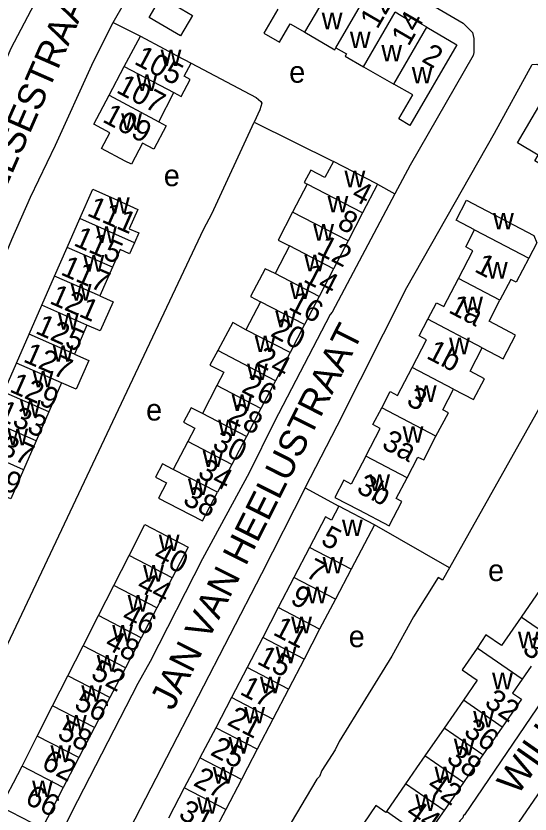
# Model space of a CAD drawing. Extents: x 159700 to 161346, y 381730 to 382922.
# Drawn here: x 160744.8 to 160840.3, y 381991.4 to 382139.7 of the extents above; entities that cross this region are included whole.
import ezdxf

# ---------------------------------------------------------------- set-up
doc = ezdxf.new("R2010")
doc.units = 0
for name, color, linetype in [('BLT_Basislijn', 7, 'Continuous'), ('BLT_Bebouwing', 7, 'Continuous'), ('BLT_Centroide', 7, 'Continuous'), ('BLT_Huisnummer', 7, 'Continuous'), ('BLT_Huisnummer_ tussenligend', 7, 'Continuous'), ('BLT_Onderverdeling_panden', 7, 'Continuous'), ('BLT_Straatnaam', 7, 'Continuous')]:
    doc.layers.add(name, color=color, linetype=linetype)

msp = doc.modelspace()

# ---------------------------------------------------------------- linework, layer by layer
at = {"layer": 'BLT_Basislijn'}
for p, q in [((160762.83, 382138.43), (160767.88, 382135.88)), ((160789.01, 382119.93), (160803.75, 382112.64)), ((160811.93, 382108.39), (160815.18, 382106.64)), ((160798.48, 382052.02), (160804.76, 382048.6)), ((160825.28, 382037.17), (160811.35, 382045.16))]:
    msp.add_line(p, q, dxfattribs=at)
for points in [[(160762.83, 382138.43), (160777.07, 382163.35), (160777.98, 382164.11), (160779.97, 382165.1)], [(160779.97, 382165.1), (160782.68, 382164.9), (160783.96, 382164.37), (160786.64, 382162.49), (160793.84, 382158.54), (160804.07, 382152.25), (160827.87, 382138.34), (160829.56, 382136.57), (160829.84, 382135.46), (160829.82, 382132.85), (160829.69, 382132.32), (160817.98, 382111.93), (160815.18, 382106.64)], [(160736.77, 382117.18), (160743.9, 382133.7), (160755.59, 382155.95), (160755.73, 382156.22)], [(160715.43, 382001.34), (160706.86, 382005.62), (160706.44, 382006.13), (160706.37, 382006.99), (160712.72, 382022.39), (160715.55, 382029.86), (160718.04, 382035.66), (160727.65, 382059.9), (160733.57, 382072.85), (160744.01, 382098.14), (160747.46, 382106.03), (160752.09, 382115.65), (160758.89, 382130.51), (160762.59, 382138.01), (160762.83, 382138.43)], [(160777.33, 382130.86), (160789.38, 382124.51), (160790.24, 382123.78), (160790.46, 382123.46), (160790.08, 382122.22), (160789.01, 382119.93)], [(160798.48, 382052.02), (160804.47, 382063.53), (160817.41, 382089.21), (160833.68, 382117.89), (160840.69, 382130.67), (160841.52, 382130.73), (160858.53, 382121.03), (160862.21, 382118.57), (160868.46, 382114.9), (160869.55, 382114.27)], [(160729.44, 381993.93), (160779.67, 382100.1), (160781.16, 382102.9), (160789.01, 382119.93)], [(160815.18, 382106.64), (160803.51, 382084.65), (160803.12, 382084.2), (160792.72, 382064.24), (160788.1, 382054.81), (160779.42, 382038.85), (160769.7, 382019.74), (160767.41, 382015.7), (160755.12, 381991.74), (160751.34, 381984.02), (160750.55, 381983.57), (160749.53, 381983.44), (160729.44, 381993.93)], [(160855.2, 382089.81), (160851, 382082.65), (160843.02, 382068.68), (160825.28, 382037.17)], [(160883.99, 382072.81), (160870.54, 382052.66), (160865.04, 382045.05), (160858.65, 382035.7), (160858.47, 382035.66), (160858.03, 382034.8), (160853.13, 382028.14), (160852.91, 382027.61), (160852.73, 382027.57), (160828.11, 381991.25), (160827.9, 381991.18), (160827.79, 381990.75), (160827.27, 381990.23), (160823.65, 381984.68), (160823.44, 381984.61), (160821.73, 381981.82), (160817.59, 381976.14), (160816.77, 381975.28), (160804.69, 381957.09), (160803.57, 381956.03), (160800.6, 381955.73), (160797.89, 381956.96), (160781.74, 381965.52)], [(160798.48, 382052.02), (160790.41, 382036.07), (160760.95, 381979.11), (160761.51, 381976.41), (160762.27, 381975.47), (160781.74, 381965.52)], [(160825.28, 382037.17), (160824.03, 382034.87), (160823.19, 382035.33), (160818.63, 382028.05), (160814.57, 382020.77), (160804.81, 382004.89), (160804.06, 382003.36), (160801.59, 381999.49), (160801.14, 381998.42), (160800.64, 381997.89), (160789.12, 381978.49), (160785.84, 381973.29), (160781.74, 381965.52)], [(160855.12, 382014.54), (160854.65, 382013.88), (160825.11, 381970.95)]]:
    msp.add_lwpolyline(points, dxfattribs=at)
at = {"layer": 'BLT_Bebouwing'}
for p, q in [((160764.9, 382130.27), (160767.88, 382135.88)), ((160762.06, 382124.92), (160764.9, 382130.27)), ((160809.33, 382130.23), (160814.97, 382127)), ((160771.31, 382120.01), (160774.1, 382125.44)), ((160811.93, 382108.39), (160809.17, 382103.07)), ((160809.17, 382103.07), (160806.47, 382097.88)), ((160754.29, 382096.67), (160756.65, 382102.04)), ((160806.47, 382097.88), (160803.77, 382092.69)), ((160751.93, 382091.3), (160754.29, 382096.67)), ((160762.69, 382092.99), (160760.34, 382087.65)), ((160803.77, 382092.69), (160801.1, 382087.55)), ((160749.58, 382085.92), (160751.93, 382091.3)), ((160801.1, 382087.55), (160798.39, 382082.34)), ((160790.2, 382086.59), (160787.49, 382081.38)), ((160747.22, 382080.55), (160749.58, 382085.92)), ((160757.97, 382082.24), (160755.62, 382076.86)), ((160798.39, 382082.34), (160795.68, 382077.12)), ((160744.86, 382075.17), (160747.22, 382080.55)), ((160795.68, 382077.12), (160792.97, 382071.91)), ((160742.51, 382069.8), (160744.86, 382075.17)), ((160753.26, 382071.49), (160750.9, 382066.12)), ((160792.97, 382071.91), (160790.28, 382066.75)), ((160782.09, 382071), (160779.4, 382065.82)), ((160790.28, 382066.75), (160787.58, 382061.56)), ((160750.9, 382066.12), (160748.55, 382060.74)), ((160748.55, 382060.74), (160746.19, 382055.37)), ((160787.58, 382061.56), (160784.88, 382056.37)), ((160776.7, 382060.63), (160774, 382055.44)), ((160784.88, 382056.37), (160782.19, 382051.18)), ((160802.28, 382046.61), (160799.31, 382040.91)), ((160811.35, 382045.16), (160807.02, 382036.88)), ((160799.31, 382040.91), (160796.4, 382035.34)), ((160762.97, 382033.87), (160765.81, 382039.46)), ((160807.02, 382036.88), (160804.12, 382031.32)), ((160773.82, 382035.3), (160770.93, 382029.74)), ((160796.4, 382035.34), (160793.5, 382029.76)), ((160760.12, 382028.28), (160762.97, 382033.87)), ((160842.13, 382033.13), (160838.59, 382028.01)), ((160804.12, 382031.32), (160801.17, 382025.77)), ((160770.93, 382029.74), (160768.03, 382024.17)), ((160793.5, 382029.76), (160790.62, 382024.24)), ((160757.28, 382022.69), (160760.12, 382028.28)), ((160801.17, 382025.77), (160798.32, 382020.22)), ((160768.03, 382024.17), (160765.14, 382018.6)), ((160790.62, 382024.24), (160787.71, 382018.65)), ((160754.43, 382017.1), (160757.28, 382022.69)), ((160798.32, 382020.22), (160795.4, 382014.63)), ((160765.14, 382018.6), (160762.24, 382013.04)), ((160787.71, 382018.65), (160784.79, 382013.06)), ((160840.49, 382018.92), (160838.8, 382016.48)), ((160751.59, 382011.5), (160754.43, 382017.1)), ((160838.8, 382016.48), (160837.02, 382013.89)), ((160795.4, 382014.63), (160792.49, 382009.04)), ((160762.24, 382013.04), (160759.35, 382007.47)), ((160784.79, 382013.06), (160781.88, 382007.46)), ((160827.9, 382012.57), (160824.32, 382007.4)), ((160748.74, 382005.91), (160751.59, 382011.5)), ((160792.49, 382009.04), (160789.57, 382003.45)), ((160759.35, 382007.47), (160756.45, 382001.9)), ((160781.88, 382007.46), (160778.96, 382001.87)), ((160824.32, 382007.4), (160820.74, 382002.23)), ((160835.08, 382007.59), (160831.47, 382002.44)), ((160786.65, 381997.86), (160783.73, 381992.27)), ((160817.16, 381997.06), (160813.58, 381991.9)), ((160827.88, 381997.28), (160824.3, 381992.11)), ((160776.05, 381996.28), (160773.13, 381990.68)), ((160783.73, 381992.27), (160780.81, 381986.67)), ((160824.3, 381992.11), (160820.73, 381986.94))]:
    msp.add_line(p, q, dxfattribs=at)
for points in [[(160781.42, 382146.23), (160778.2, 382148.11), (160774.4, 382141.59), (160777.55, 382139.75), (160775.34, 382135.97), (160773.84, 382136.84), (160769.52, 382139.36), (160781.77, 382160.35), (160787.63, 382156.93), (160787.38, 382156.48)], [(160793.41, 382140.93), (160790.82, 382136.49), (160793.74, 382134.79), (160795.74, 382138.21), (160798.45, 382136.63)], [(160821.09, 382137.55), (160818.05, 382139.32), (160817.77, 382138.84), (160815.2, 382140.34)], [(160798.45, 382136.63), (160804.02, 382133.38)], [(160821.09, 382137.55), (160826.69, 382134.27), (160817.97, 382119.33), (160815.9, 382120.54), (160818.49, 382124.99), (160814.97, 382127)], [(160767.88, 382135.88), (160772.29, 382133.53), (160774.61, 382132.3), (160777.33, 382130.86)], [(160804.02, 382133.38), (160804.22, 382133.73)], [(160804.22, 382133.73), (160806.15, 382132.6), (160805.91, 382132.19), (160809.33, 382130.23)], [(160774.1, 382125.44), (160775.45, 382124.72), (160777.14, 382127.88), (160776.03, 382128.47), (160777.33, 382130.86)], [(160771.31, 382120.01), (160772.69, 382119.27), (160770.38, 382114.92), (160768.31, 382116.02), (160766.23, 382112.11), (160765.09, 382112.71), (160760.67, 382115.05), (160762.23, 382117.97), (160759.22, 382119.57), (160762.06, 382124.92)], [(160845.48, 382110.24), (160841.18, 382112.78), (160841.78, 382113.81), (160837.92, 382116.09), (160842.33, 382123.57), (160847.52, 382120.51), (160848.28, 382121.81), (160851.26, 382120.05)], [(160803.75, 382112.64), (160802.18, 382109.63), (160799.52, 382111.01), (160798.32, 382108.71), (160798.88, 382108.41)], [(160811.93, 382108.39), (160807.5, 382110.69), (160803.75, 382112.64)], [(160798.88, 382108.41), (160796.17, 382103.2)], [(160756.65, 382102.04), (160759.03, 382107.48), (160763.61, 382105.47), (160767.4, 382103.73), (160765.83, 382100.15), (160767.59, 382099.37), (160766.77, 382097.52)], [(160829.98, 382099.92), (160826.52, 382101.73), (160828.47, 382105.45), (160840.98, 382098.91), (160841.55, 382097.53), (160840.05, 382094.65)], [(160796.17, 382103.2), (160793.49, 382098.04), (160795.59, 382096.95)], [(160826.96, 382090.89), (160829.67, 382096.05), (160828.33, 382096.75), (160829.98, 382099.92)], [(160766.77, 382097.52), (160765.88, 382095.49), (160764.12, 382096.26), (160762.69, 382092.99)], [(160795.59, 382096.95), (160792.91, 382091.8)], [(160840.05, 382094.65), (160837.71, 382090.19), (160836.69, 382090.72), (160834.67, 382086.86)], [(160792.91, 382091.8), (160791.05, 382092.72), (160788.35, 382087.53), (160790.2, 382086.59)], [(160821.31, 382083.32), (160822.92, 382086.38), (160824.24, 382085.69), (160826.96, 382090.89)], [(160760.34, 382087.65), (160762.82, 382086.56), (160760.44, 382081.15), (160757.97, 382082.24)], [(160831.4, 382078.01), (160835.26, 382075.98), (160837.59, 382080.4), (160833.72, 382082.44), (160832.65, 382083), (160834.67, 382086.86)], [(160818.37, 382074.39), (160821.06, 382079.52), (160819.7, 382080.23), (160821.31, 382083.32)], [(160787.49, 382081.38), (160785.06, 382082.7), (160782.27, 382077.51)], [(160782.27, 382077.51), (160780.81, 382074.8), (160783.38, 382073.47), (160782.09, 382071)], [(160826.07, 382070.36), (160829.77, 382068.42), (160831.79, 382072.27), (160829.13, 382073.67), (160831.4, 382078.01)], [(160755.62, 382076.86), (160758.3, 382075.68), (160755.95, 382070.32), (160753.26, 382071.49)], [(160812.71, 382066.86), (160814.29, 382069.88), (160815.65, 382069.18), (160818.37, 382074.39)], [(160822.8, 382061.58), (160825.1, 382065.96), (160824.05, 382066.51), (160826.07, 382070.36)], [(160779.4, 382065.82), (160777.31, 382066.9), (160775.9, 382064.19), (160777.99, 382063.11), (160776.7, 382060.63)], [(160809.74, 382057.91), (160812.43, 382063.05), (160811.08, 382063.75), (160812.71, 382066.86)], [(160817.44, 382053.89), (160819.45, 382057.74), (160820.51, 382057.19), (160822.8, 382061.58)], [(160746.19, 382055.37), (160743.83, 382049.99), (160739.98, 382051.6), (160735.4, 382053.61), (160737.79, 382059.05)], [(160809.74, 382057.91), (160807.03, 382052.71), (160805.67, 382053.42), (160804.01, 382050.24), (160808.44, 382047.92), (160814.1, 382044.96), (160816.46, 382049.49), (160815.42, 382050.03), (160817.44, 382053.89)], [(160774, 382055.44), (160771.97, 382056.49), (160770.68, 382054.01), (160772.71, 382052.96), (160771.23, 382050.11), (160774.98, 382048.17), (160779.42, 382045.86), (160782.19, 382051.18)], [(160804.76, 382048.6), (160803.41, 382046.02), (160802.28, 382046.61)], [(160811.35, 382045.16), (160804.76, 382048.6)], [(160765.81, 382039.46), (160768.73, 382045.2), (160776.79, 382041.01), (160773.82, 382035.3)], [(160838.59, 382028.01), (160834.95, 382022.75), (160832.08, 382024.74), (160830.44, 382022.24)], [(160830.44, 382022.24), (160827.64, 382018.2), (160830.45, 382016.26), (160827.9, 382012.57)], [(160837.02, 382013.89), (160838.68, 382012.73), (160835.08, 382007.59)], [(160745.9, 382000.32), (160748.74, 382005.91)], [(160789.57, 382003.45), (160787.76, 382000), (160786.65, 381997.86)], [(160756.45, 382001.9), (160755.46, 382000), (160753.56, 381996.34)], [(160778.96, 382001.87), (160777.99, 382000), (160776.05, 381996.28)], [(160820.74, 382002.23), (160819.2, 382000), (160817.16, 381997.06)], [(160831.47, 382002.44), (160829.76, 382000), (160827.88, 381997.28)], [(160753.56, 381996.34), (160749.64, 381988.8), (160741.98, 381992.78), (160744.29, 381997.22), (160745.9, 382000.32)], [(160813.58, 381991.9), (160813.47, 381991.73), (160811.64, 381993), (160808.19, 381988.01), (160810.01, 381986.73)]]:
    msp.add_lwpolyline(points, dxfattribs=at)
at = {"layer": 'BLT_Onderverdeling_panden'}
for p, q in [((160798.45, 382136.63), (160804.26, 382146.65)), ((160804.22, 382133.73), (160809.84, 382143.44)), ((160809.33, 382130.23), (160815.2, 382140.34)), ((160814.97, 382127), (160821.09, 382137.55)), ((160764.9, 382130.27), (160774.1, 382125.44)), ((160762.06, 382124.92), (160771.31, 382120.01)), ((160809.17, 382103.07), (160798.88, 382108.41)), ((160806.47, 382097.88), (160796.17, 382103.2)), ((160766.77, 382097.52), (160756.65, 382102.04)), ((160829.98, 382099.92), (160840.05, 382094.65)), ((160762.69, 382092.99), (160754.29, 382096.67)), ((160803.77, 382092.69), (160795.59, 382096.95)), ((160760.34, 382087.65), (160751.93, 382091.3)), ((160801.1, 382087.55), (160792.91, 382091.8)), ((160834.67, 382086.86), (160826.96, 382090.89)), ((160798.39, 382082.34), (160790.2, 382086.59)), ((160757.97, 382082.24), (160749.58, 382085.92)), ((160831.4, 382078.01), (160821.31, 382083.32)), ((160755.62, 382076.86), (160747.22, 382080.55)), ((160795.68, 382077.12), (160787.49, 382081.38)), ((160792.97, 382071.91), (160782.27, 382077.51)), ((160753.26, 382071.49), (160744.86, 382075.17)), ((160826.07, 382070.36), (160818.37, 382074.39)), ((160750.9, 382066.12), (160742.51, 382069.8)), ((160790.28, 382066.75), (160782.09, 382071)), ((160822.8, 382061.58), (160812.71, 382066.86)), ((160787.58, 382061.56), (160779.4, 382065.82)), ((160748.55, 382060.74), (160740.15, 382064.42)), ((160784.88, 382056.37), (160776.7, 382060.63)), ((160746.19, 382055.37), (160737.79, 382059.05)), ((160817.44, 382053.89), (160809.74, 382057.91)), ((160782.19, 382051.18), (160774, 382055.44)), ((160807.02, 382036.88), (160799.31, 382040.91)), ((160773.82, 382035.3), (160765.81, 382039.46)), ((160804.12, 382031.32), (160796.4, 382035.34)), ((160770.93, 382029.74), (160762.97, 382033.87)), ((160801.17, 382025.77), (160793.5, 382029.76)), ((160768.03, 382024.17), (160760.12, 382028.28)), ((160845.75, 382023.05), (160838.59, 382028.01)), ((160798.32, 382020.22), (160790.62, 382024.24)), ((160765.14, 382018.6), (160757.28, 382022.69)), ((160838.8, 382016.48), (160830.44, 382022.24)), ((160795.4, 382014.63), (160787.71, 382018.65)), ((160792.49, 382009.04), (160784.79, 382013.06)), ((160835.08, 382007.59), (160827.9, 382012.57)), ((160789.57, 382003.45), (160781.88, 382007.46)), ((160831.47, 382002.44), (160824.32, 382007.4)), ((160786.65, 381997.86), (160778.96, 382001.87)), ((160827.88, 381997.28), (160820.74, 382002.23)), ((160824.3, 381992.11), (160817.16, 381997.06)), ((160783.73, 381992.27), (160776.05, 381996.28)), ((160820.73, 381986.94), (160813.58, 381991.9))]:
    msp.add_line(p, q, dxfattribs=at)
for points in [[(160762.24, 382013.04), (160754.43, 382017.1)], [(160759.35, 382007.47), (160751.59, 382011.5)], [(160756.45, 382001.9), (160748.74, 382005.91)], [(160753.56, 381996.34), (160745.9, 382000.32)]]:
    msp.add_lwpolyline(points, dxfattribs=at)

# ---------------------------------------------------------------- texts
at = {"layer": 'BLT_Centroide'}
for s, p in [('w', (160801.57, 382137.2)), ('w', (160806.8, 382133.68)), ('w', (160771.64, 382130.34)), ('w', (160812.64, 382131.22)), ('e', (160795.53, 382127.26)), ('w', (160818.3, 382127.13)), ('w', (160767.17, 382125.75)), ('w', (160764.31, 382118.48)), ('e', (160772.24, 382108.04)), ('w', (160805.8, 382107.84)), ('w', (160762.04, 382102.91)), ('w', (160802.65, 382103.16)), ('w', (160833.4, 382100.01)), ('w', (160799.99, 382097.94)), ('w', (160759.66, 382097.5)), ('w', (160757.3, 382092.16)), ('w', (160798.34, 382092.25)), ('w', (160832.26, 382090.88)), ('w', (160754.95, 382086.78)), ('w', (160795.65, 382087.06)), ('w', (160827.67, 382084.47)), ('w', (160752.59, 382081.41)), ('w', (160792.94, 382081.84)), ('w', (160789.12, 382077.22)), ('w', (160825.23, 382076.84)), ('w', (160751.59, 382075.44)), ('w', (160787.69, 382072.03)), ('w', (160747.88, 382070.66)), ('w', (160819.05, 382067.97)), ('w', (160745.52, 382065.28)), ('w', (160784.84, 382066.28)), ('e', (160768.95, 382064.51)), ('w', (160782.33, 382061.62)), ('w', (160743.16, 382059.91)), ('w', (160816.6, 382060.38)), ('w', (160779.45, 382055.91)), ('w', (160776.71, 382050.66)), ('w', (160810.4, 382051.44)), ('w', (160805.33, 382043.05)), ('w', (160771.3, 382040.25)), ('w', (160801.72, 382036.12)), ('w', (160768.4, 382034.59)), ('e', (160832.47, 382034.7)), ('w', (160798.8, 382030.56)), ('w', (160765.52, 382029.03)), ('w', (160795.89, 382025)), ('w', (160762.66, 382023.44)), ('e', (160806.59, 382022.41)), ('w', (160838.02, 382022.22)), ('w', (160793.02, 382019.44)), ('w', (160759.79, 382017.88)), ('w', (160790.1, 382013.84)), ('w', (160833.22, 382014.59)), ('w', (160756.91, 382012.28)), ('w', (160787.18, 382008.25)), ('w', (160829.7, 382007.5)), ('w', (160754.05, 382006.72)), ('w', (160784.27, 382002.66)), ('w', (160826.11, 382002.34)), ('w', (160751.18, 382001.12)), ('w', (160781.34, 381997.06)), ('w', (160822.52, 381997.16)), ('w', (160747.77, 381994.56)), ('w', (160778.43, 381991.47)), ('w', (160818.95, 381992))]:
    msp.add_text(s, height=4, dxfattribs=at).set_placement(p)
at = {"layer": 'BLT_Huisnummer'}
for s, rotation, p in [('14', 59.8698, (160817.7, 382133.87)), ('105', 332.0306, (160766.54, 382130.85)), ('2', 330.2017, (160819.95, 382131.3)), ('109', 332.0205, (160760.66, 382120.1)), ('4', 332.5962, (160806.9, 382105.73)), ('111', 336.3109, (160757.79, 382102.67)), ('8', 332.5962, (160804.24, 382100.4)), ('12', 332.5962, (160800.46, 382095.61)), ('1', 332.3865, (160829.75, 382092.28)), ('117', 336.3109, (160752.9, 382091.69)), ('121', 336.3109, (160750.83, 382086.35)), ('16', 332.5962, (160795.2, 382085.28)), ('1a', 332.3873, (160824.95, 382084.67)), ('125', 336.3109, (160748.19, 382080.79)), ('20', 332.5962, (160791.87, 382080.31)), ('1b', 332.3841, (160820.81, 382076.19)), ('24', 332.5962, (160789.11, 382075.01)), ('129', 336.3109, (160743.4, 382069.95)), ('26', 332.5962, (160786.48, 382069.9)), ('3', 332.389, (160817.1, 382067.56)), ('133', 336.3109, (160741.17, 382064.84)), ('28', 332.5962, (160783.93, 382064.54)), ('3a', 332.3899, (160812.52, 382059.48)), ('139', 336.3214, (160736.53, 382054.22)), ('34', 332.5962, (160778.32, 382054.14)), ('3b', 332.3908, (160807.83, 382051.3)), ('38', 332.5962, (160775.57, 382049.1)), ('5', 332.5962, (160801.2, 382041.67)), ('40', 332.5962, (160770.1, 382038.7)), ('44', 332.5962, (160766.99, 382033.09)), ('9', 332.5962, (160795.52, 382030.67)), ('48', 332.5962, (160761.06, 382022.36)), ('30', 325.3165, (160838.64, 382021.55)), ('15', 332.5962, (160789.34, 382019.44)), ('52', 332.5962, (160758.46, 382016.76)), ('17', 332.5962, (160786.18, 382013.77)), ('56', 332.5962, (160755.36, 382011.14)), ('32', 325.3165, (160831.59, 382011.68)), ('21', 332.5962, (160783.81, 382008.09)), ('58', 332.5962, (160752.25, 382005.65)), ('36', 325.3165, (160827.74, 382006.28)), ('25', 332.5962, (160780.69, 382002.5)), ('62', 332.5962, (160749.31, 382000.04)), ('38', 325.3165, (160824.53, 382001.3)), ('27', 332.5962, (160777.53, 381996.83)), ('42', 325.3165, (160820.91, 381996.21)), ('66', 332.5962, (160746.25, 381993.52)), ('31', 332.5962, (160774.77, 381990.74)), ('44', 325.3165, (160816.95, 381991.13))]:
    msp.add_text(s, height=4, rotation=rotation, dxfattribs=at).set_placement(p)
at = {"layer": 'BLT_Huisnummer_ tussenligend'}
for s, rotation, p in [('12', 59.8649, (160811.89, 382137.05)), ('107', 332.0306, (160763.21, 382125.55)), ('115', 336.3109, (160755.3, 382097.11)), ('14', 332.5962, (160797.97, 382090.41)), ('127', 336.3109, (160745.94, 382075.53)), ('137', 336.3192, (160738.81, 382059.59)), ('30', 332.5962, (160781.03, 382059.44)), ('7', 332.5962, (160798.35, 382035.59)), ('46', 332.5962, (160764.19, 382027.28)), ('11', 332.5962, (160792.32, 382024.83))]:
    msp.add_text(s, height=4, rotation=rotation, dxfattribs=at).set_placement(p)
at = {"layer": 'BLT_Straatnaam'}
for s, height, rotation, p in [('GESTELSESTRAAT', 5, 66.3471, (160734.94, 382089.34)), ('JAN VAN HEELUSTRAAT', 4.9999, 63.2877, (160773.92, 382010.45)), ('WILLEM KLOOSLAAN', 5, 55.0394, (160837.92, 381994.69))]:
    msp.add_text(s, height=height, rotation=rotation, dxfattribs=at).set_placement(p)

doc.saveas('drawing.dxf')
